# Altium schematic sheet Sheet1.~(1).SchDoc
size A; SheetNumber: 1; SheetTotal: 3
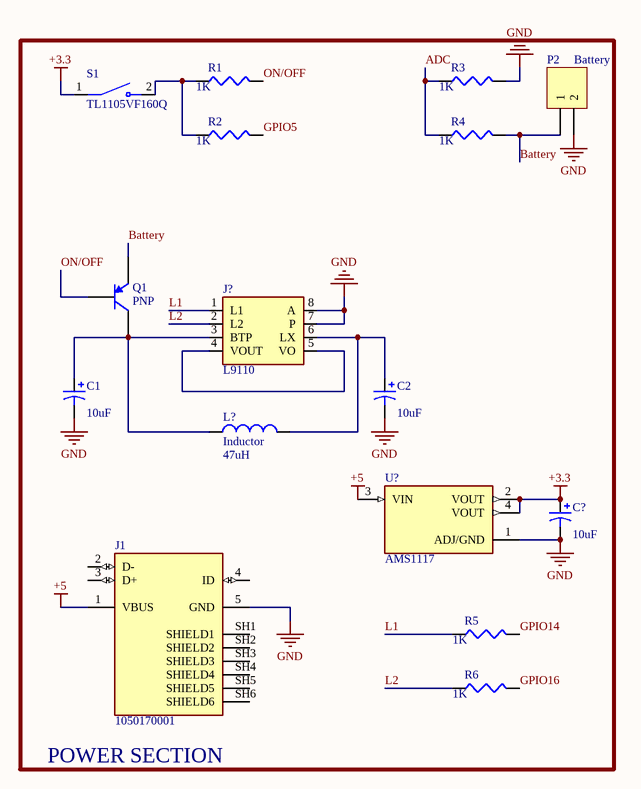
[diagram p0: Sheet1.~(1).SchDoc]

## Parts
C1  value 10uF  [C2225]
C2  value 10uF  [C2225]
C?  value 10uF  [C2225]
J1  1050170001  [MOLEX_1050170001]
J?  L9110  [SO-08]
L?  Inductor  value 47uH  [INDC3216]
P2  Battery  [HDR1X2]
Q1  PNP  [SOT-23B_N]
R1  value 1K  [14-1210]
R2  value 1K  [14-1210]
R3  value 1K  [14-1210]
R4  value 1K  [14-1210]
R5  value 1K  [14-1210]
R6  value 1K  [14-1210]
S1  TL1105VF160Q  [SW_TL1105VF160Q]
U?  AMS1117  [SOT229P700X180-4N]

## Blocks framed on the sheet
POWER SECTION: C1 C2 C? J1 J? L? P2 Q1 R1-R6 S1 U?

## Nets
+3.3: C?.1 S1.1 U?.2(VOUT) U?.4(VOUT)
+5: J1.1(VBUS) U?.3(VIN)
GND: C1.2 C2.2 C?.2 J1.5(GND) J?.7(P) J?.8(A) P2.2 R3.2 U?.1(ADJ/GND)
ADC: R3.1 R4.1
Battery: P2.1 Q1.3(E) R4.2
GPIO5: R2.2
GPIO14: R5.2
GPIO16: R6.2
L1: J?.1(L1) R5.1
L2: J?.2(L2) R6.1
ON/OFF: Q1.2(B) R1.2
NetC1_1: C1.1 J?.3(BTP) L?.1 Q1.1(C)
NetC2_1: C2.1 J?.6(LX) L?.2
NetJ?_4: J?.4(VOUT) J?.5(VO)
NetR1_1: R1.1 R2.1 S1.2

Not connected (* = marked no-connect by the designer): J1 2(D-) 3(D+) 4(ID) SH1(SHIELD1) SH2(SHIELD2) SH3(SHIELD3) SH4(SHIELD4) SH5(SHIELD5) SH6(SHIELD6)

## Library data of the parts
C1 C2 C? = Cap Pol3: Polarized Capacitor (Surface Mount)
J1 = 1050170001: USB - micro B USB 2.0 Receptacle Connector 5 Position Surface Mount, Right Angle; Through Hole; MF: Molex
J? = L9110: Motor control driver chip; MF: Asic; MP: L9110 (SOP-8)
L? = Inductor: Code_IEC: 1005
P2 = Header 2: Header, 2-Pin
Q1 = PNP: PNP Bipolar Transistor
R1-R6 = Res3: Resistor
S1 = TL1105VF160Q: Tactile Switch, TL1105 Series, SPST-NO, 3.85mm Side Actuated, 0.05A, 12VDC, PC ¦ E-Switch TL1105VF160Q
U? = AMS1117: 1A LOW DROPOUT VOLTAGE REGULATOR SOT-223; MF: Advanced Monolithic Systems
